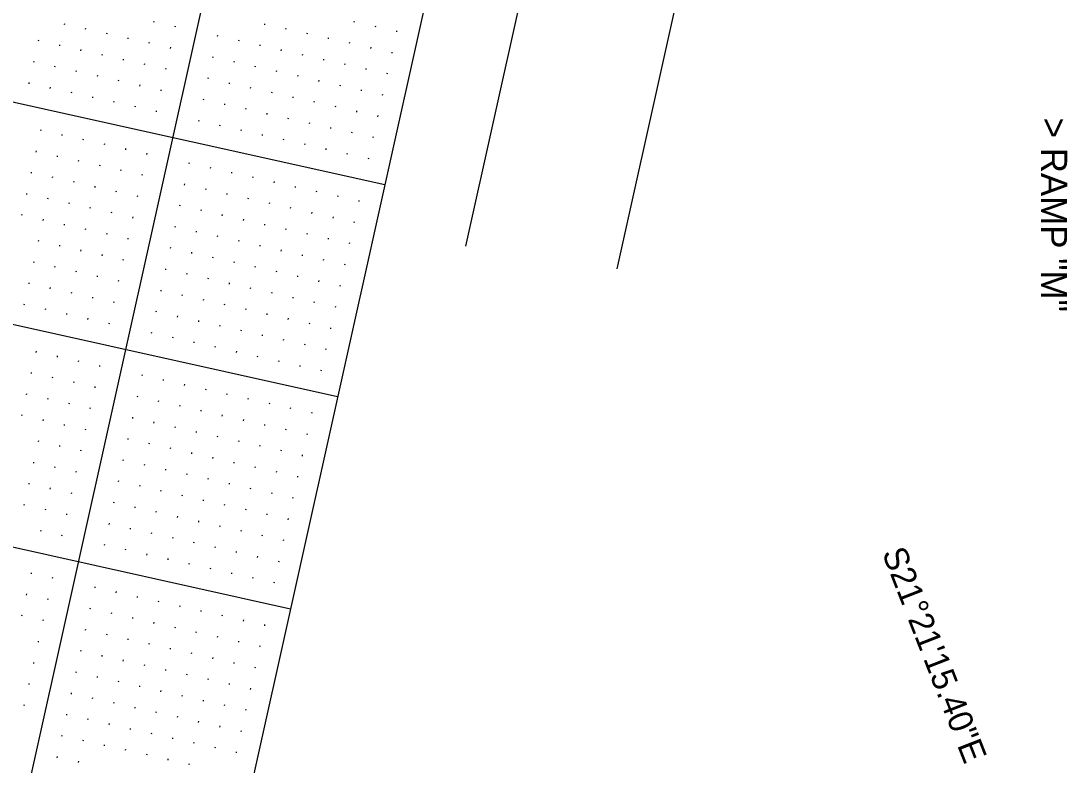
# Model space of a CAD drawing. Extents: x 2149268 to 2150830, y 142155 to 144285.
# Drawn here: x 2149963 to 2150201.6, y 143013.1 to 143184.5 of the extents above; entities that cross this region are included whole.
import ezdxf

# ---------------------------------------------------------------- set-up
doc = ezdxf.new("R2010")
doc.units = 0
for name, color, linetype in [('PR_Align_Ramp_M_Label', 7, 'Continuous'), ('PR_Align_Ramp_M_Leader', 7, 'Continuous'), ('SHT_Profile_Grid_Major', 7, 'Continuous'), ('SHT_Profile_Grid_Minor', 7, 'Continuous'), ('SHT_Sheet_Border', 7, 'Continuous')]:
    doc.layers.add(name, color=color, linetype=linetype)

msp = doc.modelspace()

# ---------------------------------------------------------------- linework, layer by layer
at = {"layer": 'PR_Align_Ramp_M_Leader'}
for points in [[(2150242.97, 143380.57), (2150121.59, 143385.32), (2150065.39, 143132.57)], [(2150212.94, 143229.67), (2150185.56, 143322.04), (2150145.43, 143330.97), (2150100.17, 143127.41)]]:
    msp.add_lwpolyline(points, dxfattribs=at)
at = {"layer": 'SHT_Profile_Grid_Major'}
for p, q in [((2150158.06, 143877.55), (2149816.2, 142340.1)), ((2149558.71, 143255.31), (2150046.79, 143146.78)), ((2149547.86, 143206.5), (2150035.94, 143097.97)), ((2149537.01, 143157.69), (2150025.09, 143049.16)), ((2149537.01, 143157.69), (2150025.09, 143049.16))]:
    msp.add_line(p, q, dxfattribs=at)
at = {"layer": 'SHT_Profile_Grid_Minor'}
for p, q in [((2149973.07, 143183.79), (2149973.01, 143183.54)), ((2149993.67, 143184.33), (2149993.62, 143184.08)), ((2149998.56, 143183.24), (2149998.5, 143183)), ((2150019.16, 143183.78), (2150019.11, 143183.54)), ((2150039.77, 143184.32), (2150039.72, 143184.08)), ((2150044.65, 143183.24), (2150044.6, 143182.99)), ((2149977.95, 143182.7), (2149977.89, 143182.46)), ((2149982.83, 143181.62), (2149982.77, 143181.37)), ((2149987.71, 143180.53), (2149987.65, 143180.29)), ((2150008.32, 143181.07), (2150008.26, 143180.83)), ((2150024.05, 143182.7), (2150023.99, 143182.45)), ((2150028.93, 143181.61), (2150028.87, 143181.37)), ((2150033.81, 143180.53), (2150033.75, 143180.28)), ((2150049.53, 143182.15), (2150049.48, 143181.91)), ((2149967.1, 143179.99), (2149967.05, 143179.75)), ((2149971.98, 143178.91), (2149971.93, 143178.66)), ((2149992.59, 143179.45), (2149992.54, 143179.2)), ((2149997.47, 143178.36), (2149997.42, 143178.12)), ((2150013.2, 143179.99), (2150013.14, 143179.74)), ((2150018.08, 143178.9), (2150018.02, 143178.66)), ((2150038.69, 143179.44), (2150038.63, 143179.2)), ((2150043.57, 143178.36), (2150043.51, 143178.11)), ((2149976.86, 143177.82), (2149976.81, 143177.58)), ((2149981.74, 143176.74), (2149981.69, 143176.49)), ((2150007.23, 143176.19), (2150007.18, 143175.95)), ((2150022.96, 143177.82), (2150022.91, 143177.57)), ((2150027.84, 143176.73), (2150027.79, 143176.49)), ((2150048.45, 143177.27), (2150048.39, 143177.03)), ((2149966.02, 143175.11), (2149965.96, 143174.87)), ((2149970.9, 143174.03), (2149970.84, 143173.78)), ((2149986.62, 143175.65), (2149986.57, 143175.41)), ((2149991.5, 143174.57), (2149991.45, 143174.32)), ((2149996.39, 143173.48), (2149996.33, 143173.24)), ((2150012.11, 143175.11), (2150012.06, 143174.86)), ((2150016.99, 143174.02), (2150016.94, 143173.78)), ((2150032.72, 143175.65), (2150032.67, 143175.4)), ((2150037.6, 143174.56), (2150037.55, 143174.32)), ((2150042.48, 143173.47), (2150042.43, 143173.23)), ((2149975.78, 143172.94), (2149975.72, 143172.7)), ((2149980.66, 143171.86), (2149980.6, 143171.61)), ((2150006.15, 143171.31), (2150006.09, 143171.07)), ((2150021.87, 143172.94), (2150021.82, 143172.69)), ((2150026.76, 143171.85), (2150026.7, 143171.61)), ((2150047.36, 143172.39), (2150047.31, 143172.15)), ((2149964.93, 143170.23), (2149964.88, 143169.99)), ((2149969.81, 143169.15), (2149969.76, 143168.9)), ((2149985.54, 143170.77), (2149985.48, 143170.53)), ((2149990.42, 143169.69), (2149990.36, 143169.44)), ((2149995.3, 143168.6), (2149995.25, 143168.36)), ((2150011.03, 143170.22), (2150010.97, 143169.98)), ((2150015.91, 143169.14), (2150015.85, 143168.9)), ((2150031.64, 143170.76), (2150031.58, 143170.52)), ((2150036.52, 143169.68), (2150036.46, 143169.44)), ((2150041.4, 143168.59), (2150041.34, 143168.35)), ((2149974.69, 143168.06), (2149974.64, 143167.82)), ((2149979.57, 143166.97), (2149979.52, 143166.73)), ((2150005.06, 143166.43), (2150005.01, 143166.19)), ((2150020.79, 143168.05), (2150020.73, 143167.81)), ((2150025.67, 143166.97), (2150025.62, 143166.72)), ((2150046.28, 143167.51), (2150046.22, 143167.26)), ((2149984.45, 143165.89), (2149984.4, 143165.65)), ((2149989.33, 143164.8), (2149989.28, 143164.56)), ((2150009.94, 143165.34), (2150009.89, 143165.1)), ((2150014.82, 143164.26), (2150014.77, 143164.01)), ((2150030.55, 143165.88), (2150030.5, 143165.64)), ((2150035.43, 143164.8), (2150035.38, 143164.55)), ((2149994.21, 143163.72), (2149994.16, 143163.48)), ((2150003.98, 143161.55), (2150003.92, 143161.3)), ((2150019.7, 143163.17), (2150019.65, 143162.93)), ((2150024.58, 143162.09), (2150024.53, 143161.84)), ((2150040.31, 143163.71), (2150040.26, 143163.47)), ((2150045.19, 143162.63), (2150045.14, 143162.38)), ((2149967.64, 143159.38), (2149967.59, 143159.14)), ((2150008.86, 143160.46), (2150008.8, 143160.22)), ((2150013.74, 143159.38), (2150013.68, 143159.13)), ((2150029.47, 143161), (2150029.41, 143160.76)), ((2150034.35, 143159.92), (2150034.29, 143159.67)), ((2149972.52, 143158.3), (2149972.47, 143158.05)), ((2149977.4, 143157.21), (2149977.35, 143156.97)), ((2150018.62, 143158.29), (2150018.56, 143158.05)), ((2150023.5, 143157.21), (2150023.45, 143156.96)), ((2150039.23, 143158.83), (2150039.17, 143158.59)), ((2150044.11, 143157.75), (2150044.05, 143157.5)), ((2149966.55, 143154.5), (2149966.5, 143154.26)), ((2149982.28, 143156.13), (2149982.23, 143155.88)), ((2149987.16, 143155.04), (2149987.11, 143154.8)), ((2150028.38, 143156.12), (2150028.33, 143155.88)), ((2150033.26, 143155.04), (2150033.21, 143154.79)), ((2149971.44, 143153.42), (2149971.38, 143153.17)), ((2149976.32, 143152.33), (2149976.26, 143152.09)), ((2149992.04, 143153.96), (2149991.99, 143153.71)), ((2150038.14, 143153.95), (2150038.09, 143153.71)), ((2150043.02, 143152.87), (2150042.97, 143152.62)), ((2149965.47, 143149.62), (2149965.42, 143149.38)), ((2149981.2, 143151.25), (2149981.14, 143151)), ((2149986.08, 143150.16), (2149986.02, 143149.92)), ((2150001.81, 143151.79), (2150001.75, 143151.54)), ((2150006.69, 143150.7), (2150006.63, 143150.46)), ((2150011.57, 143149.62), (2150011.51, 143149.37)), ((2149970.35, 143148.54), (2149970.3, 143148.29)), ((2149975.23, 143147.45), (2149975.18, 143147.21)), ((2149990.96, 143149.08), (2149990.9, 143148.83)), ((2150016.45, 143148.53), (2150016.39, 143148.29)), ((2150021.33, 143147.45), (2150021.27, 143147.2)), ((2149964.38, 143144.74), (2149964.33, 143144.5)), ((2149980.11, 143146.37), (2149980.06, 143146.12)), ((2149984.99, 143145.28), (2149984.94, 143145.04)), ((2150000.72, 143146.91), (2150000.67, 143146.66)), ((2150005.6, 143145.82), (2150005.55, 143145.58)), ((2150010.48, 143144.74), (2150010.43, 143144.49)), ((2150026.21, 143146.36), (2150026.16, 143146.12)), ((2150031.09, 143145.28), (2150031.04, 143145.03)), ((2149969.27, 143143.66), (2149969.21, 143143.41)), ((2149974.15, 143142.57), (2149974.09, 143142.33)), ((2149989.87, 143144.2), (2149989.82, 143143.95)), ((2150015.36, 143143.65), (2150015.31, 143143.41)), ((2150020.24, 143142.56), (2150020.19, 143142.32)), ((2150035.97, 143144.19), (2150035.92, 143143.95)), ((2150040.85, 143143.1), (2150040.8, 143142.86)), ((2149979.03, 143141.49), (2149978.97, 143141.24)), ((2149983.91, 143140.4), (2149983.85, 143140.16)), ((2149999.64, 143142.03), (2149999.58, 143141.78)), ((2150004.52, 143140.94), (2150004.46, 143140.7)), ((2150025.12, 143141.48), (2150025.07, 143141.24)), ((2150030.01, 143140.39), (2150029.95, 143140.15)), ((2149963.3, 143139.86), (2149963.24, 143139.62)), ((2149968.18, 143138.78), (2149968.13, 143138.53)), ((2149973.06, 143137.69), (2149973.01, 143137.45)), ((2149988.79, 143139.32), (2149988.73, 143139.07)), ((2150009.4, 143139.85), (2150009.34, 143139.61)), ((2150014.28, 143138.77), (2150014.22, 143138.53)), ((2150019.16, 143137.68), (2150019.1, 143137.44)), ((2150034.89, 143139.31), (2150034.83, 143139.07)), ((2150039.77, 143138.22), (2150039.71, 143137.98)), ((2149977.94, 143136.6), (2149977.89, 143136.36)), ((2149982.82, 143135.52), (2149982.77, 143135.28)), ((2149998.55, 143137.14), (2149998.5, 143136.9)), ((2150003.43, 143136.06), (2150003.38, 143135.82)), ((2150024.04, 143136.6), (2150023.98, 143136.35)), ((2150028.92, 143135.51), (2150028.87, 143135.27)), ((2149967.09, 143133.89), (2149967.04, 143133.65)), ((2149971.98, 143132.81), (2149971.92, 143132.57)), ((2149987.7, 143134.43), (2149987.65, 143134.19)), ((2150008.31, 143134.97), (2150008.26, 143134.73)), ((2150013.19, 143133.89), (2150013.14, 143133.64)), ((2150018.07, 143132.8), (2150018.02, 143132.56)), ((2150033.8, 143134.43), (2150033.75, 143134.18)), ((2150038.68, 143133.34), (2150038.63, 143133.1)), ((2149976.86, 143131.72), (2149976.8, 143131.48)), ((2149981.74, 143130.64), (2149981.68, 143130.39)), ((2149997.46, 143132.26), (2149997.41, 143132.02)), ((2150002.35, 143131.18), (2150002.29, 143130.93)), ((2150022.95, 143131.72), (2150022.9, 143131.47)), ((2150027.83, 143130.63), (2150027.78, 143130.39)), ((2149966.01, 143129.01), (2149965.96, 143128.77)), ((2149986.62, 143129.55), (2149986.56, 143129.31)), ((2150007.23, 143130.09), (2150007.17, 143129.85)), ((2150012.11, 143129.01), (2150012.05, 143128.76)), ((2150032.72, 143129.55), (2150032.66, 143129.3)), ((2150037.6, 143128.46), (2150037.54, 143128.22)), ((2149970.89, 143127.93), (2149970.84, 143127.68)), ((2149975.77, 143126.84), (2149975.72, 143126.6)), ((2149980.65, 143125.76), (2149980.6, 143125.51)), ((2149996.38, 143127.38), (2149996.33, 143127.14)), ((2150001.26, 143126.3), (2150001.21, 143126.05)), ((2150016.99, 143127.92), (2150016.93, 143127.68)), ((2150021.87, 143126.84), (2150021.81, 143126.59)), ((2150026.75, 143125.75), (2150026.7, 143125.51)), ((2149964.92, 143124.13), (2149964.87, 143123.89)), ((2149985.53, 143124.67), (2149985.48, 143124.43)), ((2150006.14, 143125.21), (2150006.09, 143124.97)), ((2150011.02, 143124.13), (2150010.97, 143123.88)), ((2150031.63, 143124.67), (2150031.58, 143124.42)), ((2150036.51, 143123.58), (2150036.46, 143123.34)), ((2149969.8, 143123.05), (2149969.75, 143122.8)), ((2149974.69, 143121.96), (2149974.63, 143121.72)), ((2149979.57, 143120.88), (2149979.51, 143120.63)), ((2149995.29, 143122.5), (2149995.24, 143122.26)), ((2150000.17, 143121.42), (2150000.12, 143121.17)), ((2150015.9, 143123.04), (2150015.85, 143122.8)), ((2150020.78, 143121.96), (2150020.73, 143121.71)), ((2149963.84, 143119.25), (2149963.78, 143119.01)), ((2149984.45, 143119.79), (2149984.39, 143119.55)), ((2150005.06, 143120.33), (2150005, 143120.09)), ((2150009.94, 143119.25), (2150009.88, 143119)), ((2150025.66, 143120.87), (2150025.61, 143120.63)), ((2150030.54, 143119.79), (2150030.49, 143119.54)), ((2150035.43, 143118.7), (2150035.37, 143118.46)), ((2149968.72, 143118.17), (2149968.67, 143117.92)), ((2149973.6, 143117.08), (2149973.55, 143116.84)), ((2149994.21, 143117.62), (2149994.15, 143117.38)), ((2149999.09, 143116.54), (2149999.04, 143116.29)), ((2150014.82, 143118.16), (2150014.76, 143117.92)), ((2150019.7, 143117.08), (2150019.64, 143116.83)), ((2149978.48, 143116), (2149978.43, 143115.75)), ((2149983.36, 143114.91), (2149983.31, 143114.67)), ((2150003.97, 143115.45), (2150003.92, 143115.21)), ((2150008.85, 143114.37), (2150008.8, 143114.12)), ((2150024.58, 143115.99), (2150024.52, 143115.75)), ((2150029.46, 143114.91), (2150029.41, 143114.66)), ((2150034.34, 143113.82), (2150034.29, 143113.58)), ((2149993.12, 143112.74), (2149993.07, 143112.5)), ((2149998, 143111.66), (2149997.95, 143111.41)), ((2150013.73, 143113.28), (2150013.68, 143113.04)), ((2150018.61, 143112.2), (2150018.56, 143111.95)), ((2150002.89, 143110.57), (2150002.83, 143110.33)), ((2150007.77, 143109.48), (2150007.71, 143109.24)), ((2150023.49, 143111.11), (2150023.44, 143110.87)), ((2150028.37, 143110.02), (2150028.32, 143109.78)), ((2149966.55, 143108.41), (2149966.49, 143108.16)), ((2149971.43, 143107.32), (2149971.38, 143107.08)), ((2150012.65, 143108.4), (2150012.59, 143108.16)), ((2150017.53, 143107.31), (2150017.47, 143107.07)), ((2150033.26, 143108.94), (2150033.2, 143108.7)), ((2149976.31, 143106.23), (2149976.26, 143105.99)), ((2149981.19, 143105.15), (2149981.14, 143104.91)), ((2150022.41, 143106.23), (2150022.35, 143105.98)), ((2150027.29, 143105.14), (2150027.23, 143104.9)), ((2149965.46, 143103.52), (2149965.41, 143103.28)), ((2149970.34, 143102.44), (2149970.29, 143102.2)), ((2149990.95, 143102.98), (2149990.9, 143102.73)), ((2149995.83, 143101.89), (2149995.78, 143101.65)), ((2150032.17, 143104.06), (2150032.12, 143103.81)), ((2149975.23, 143101.35), (2149975.17, 143101.11)), ((2149980.11, 143100.27), (2149980.05, 143100.02)), ((2150000.71, 143100.81), (2150000.66, 143100.56)), ((2150005.6, 143099.72), (2150005.54, 143099.48)), ((2149964.38, 143098.64), (2149964.32, 143098.4)), ((2149969.26, 143097.56), (2149969.2, 143097.31)), ((2149989.87, 143098.1), (2149989.81, 143097.85)), ((2150010.48, 143098.64), (2150010.42, 143098.39)), ((2150015.36, 143097.55), (2150015.3, 143097.31)), ((2149974.14, 143096.47), (2149974.09, 143096.23)), ((2149979.02, 143095.39), (2149978.97, 143095.14)), ((2149994.75, 143097.01), (2149994.69, 143096.77)), ((2149999.63, 143095.93), (2149999.57, 143095.68)), ((2150004.51, 143094.84), (2150004.46, 143094.6)), ((2150020.24, 143096.47), (2150020.18, 143096.22)), ((2150025.12, 143095.38), (2150025.06, 143095.14)), ((2149963.29, 143093.76), (2149963.24, 143093.52)), ((2149968.17, 143092.68), (2149968.12, 143092.43)), ((2149988.78, 143093.22), (2149988.73, 143092.97)), ((2150009.39, 143093.76), (2150009.34, 143093.51)), ((2150014.27, 143092.67), (2150014.22, 143092.43)), ((2150030, 143094.3), (2150029.94, 143094.05)), ((2149973.05, 143091.59), (2149973, 143091.35)), ((2149977.94, 143090.51), (2149977.88, 143090.26)), ((2149993.66, 143092.13), (2149993.61, 143091.89)), ((2149998.54, 143091.05), (2149998.49, 143090.8)), ((2150003.42, 143089.96), (2150003.37, 143089.72)), ((2150019.15, 143091.59), (2150019.1, 143091.34)), ((2150024.03, 143090.5), (2150023.98, 143090.26)), ((2149967.09, 143087.8), (2149967.03, 143087.55)), ((2149987.7, 143088.34), (2149987.64, 143088.09)), ((2150008.31, 143088.88), (2150008.25, 143088.63)), ((2150013.19, 143087.79), (2150013.13, 143087.55)), ((2150028.91, 143089.42), (2150028.86, 143089.17)), ((2149971.97, 143086.71), (2149971.92, 143086.47)), ((2149976.85, 143085.63), (2149976.8, 143085.38)), ((2149992.58, 143087.25), (2149992.52, 143087.01)), ((2149997.46, 143086.17), (2149997.4, 143085.92)), ((2150018.07, 143086.71), (2150018.01, 143086.46)), ((2150022.95, 143085.62), (2150022.89, 143085.38)), ((2149966, 143082.92), (2149965.95, 143082.67)), ((2149986.61, 143083.46), (2149986.56, 143083.21)), ((2150002.34, 143085.08), (2150002.29, 143084.84)), ((2150007.22, 143084), (2150007.17, 143083.75)), ((2150012.1, 143082.91), (2150012.05, 143082.67)), ((2150027.83, 143084.54), (2150027.77, 143084.29)), ((2149970.88, 143081.83), (2149970.83, 143081.59)), ((2149975.76, 143080.75), (2149975.71, 143080.5)), ((2149991.49, 143082.37), (2149991.44, 143082.13)), ((2149996.37, 143081.29), (2149996.32, 143081.04)), ((2150016.98, 143081.82), (2150016.93, 143081.58)), ((2150021.86, 143080.74), (2150021.81, 143080.5)), ((2149964.92, 143078.04), (2149964.86, 143077.79)), ((2149985.53, 143078.58), (2149985.47, 143078.33)), ((2150001.25, 143080.2), (2150001.2, 143079.96)), ((2150006.13, 143079.11), (2150006.08, 143078.87)), ((2150011.02, 143078.03), (2150010.96, 143077.79)), ((2150026.74, 143079.65), (2150026.69, 143079.41)), ((2149969.8, 143076.95), (2149969.74, 143076.71)), ((2149974.68, 143075.86), (2149974.63, 143075.62)), ((2149990.41, 143077.49), (2149990.35, 143077.25)), ((2149995.29, 143076.4), (2149995.23, 143076.16)), ((2150015.9, 143076.94), (2150015.84, 143076.7)), ((2150020.78, 143075.86), (2150020.72, 143075.61)), ((2149984.44, 143073.69), (2149984.39, 143073.45)), ((2150000.17, 143075.32), (2150000.11, 143075.08)), ((2150005.05, 143074.23), (2150005, 143073.99)), ((2150025.66, 143074.77), (2150025.6, 143074.53)), ((2149963.83, 143073.15), (2149963.78, 143072.91)), ((2149968.71, 143072.07), (2149968.66, 143071.83)), ((2149973.59, 143070.98), (2149973.54, 143070.74)), ((2149989.32, 143072.61), (2149989.27, 143072.36)), ((2149994.2, 143071.52), (2149994.15, 143071.28)), ((2150009.93, 143073.15), (2150009.88, 143072.9)), ((2150014.81, 143072.06), (2150014.76, 143071.82)), ((2150019.69, 143070.98), (2150019.64, 143070.73)), ((2149983.36, 143068.81), (2149983.3, 143068.57)), ((2149999.08, 143070.44), (2149999.03, 143070.19)), ((2150003.96, 143069.35), (2150003.91, 143069.11)), ((2150024.57, 143069.89), (2150024.52, 143069.65)), ((2149967.63, 143067.19), (2149967.57, 143066.94)), ((2149972.51, 143066.1), (2149972.45, 143065.86)), ((2149988.24, 143067.73), (2149988.18, 143067.48)), ((2149993.12, 143066.64), (2149993.06, 143066.4)), ((2150008.85, 143068.27), (2150008.79, 143068.02)), ((2150013.73, 143067.18), (2150013.67, 143066.94)), ((2150018.61, 143066.1), (2150018.55, 143065.85)), ((2149982.27, 143063.93), (2149982.22, 143063.69)), ((2149998, 143065.56), (2149997.94, 143065.31)), ((2150002.88, 143064.47), (2150002.82, 143064.23)), ((2150023.49, 143065.01), (2150023.43, 143064.77)), ((2149987.15, 143062.85), (2149987.1, 143062.6)), ((2149992.03, 143061.76), (2149991.98, 143061.52)), ((2150007.76, 143063.39), (2150007.71, 143063.14)), ((2150012.64, 143062.3), (2150012.59, 143062.06)), ((2149996.91, 143060.68), (2149996.86, 143060.43)), ((2150001.79, 143059.59), (2150001.74, 143059.35)), ((2150017.52, 143061.22), (2150017.47, 143060.97)), ((2150022.4, 143060.13), (2150022.35, 143059.89)), ((2149965.46, 143057.43), (2149965.4, 143057.18)), ((2150006.67, 143058.51), (2150006.62, 143058.26)), ((2150011.56, 143057.42), (2150011.5, 143057.18)), ((2149970.34, 143056.34), (2149970.28, 143056.1)), ((2149980.1, 143054.17), (2149980.05, 143053.93)), ((2150016.44, 143056.34), (2150016.38, 143056.09)), ((2150021.32, 143055.25), (2150021.26, 143055.01)), ((2149964.37, 143052.55), (2149964.32, 143052.3)), ((2149984.98, 143053.09), (2149984.93, 143052.84)), ((2149989.86, 143052), (2149989.81, 143051.76)), ((2149969.25, 143051.46), (2149969.2, 143051.22)), ((2149994.74, 143050.92), (2149994.69, 143050.67)), ((2149999.62, 143049.83), (2149999.57, 143049.59)), ((2149963.29, 143047.67), (2149963.23, 143047.42)), ((2149979.01, 143049.29), (2149978.96, 143049.05)), ((2149983.9, 143048.2), (2149983.84, 143047.96)), ((2149988.78, 143047.12), (2149988.72, 143046.88)), ((2150004.5, 143048.74), (2150004.45, 143048.5)), ((2150009.38, 143047.66), (2150009.33, 143047.42)), ((2149968.17, 143046.58), (2149968.11, 143046.34)), ((2149993.66, 143046.03), (2149993.6, 143045.79)), ((2149998.54, 143044.95), (2149998.48, 143044.71)), ((2150014.27, 143046.57), (2150014.21, 143046.33)), ((2150019.15, 143045.49), (2150019.09, 143045.24)), ((2149977.93, 143044.41), (2149977.88, 143044.17)), ((2149982.81, 143043.32), (2149982.76, 143043.08)), ((2149987.69, 143042.24), (2149987.64, 143041.99)), ((2150003.42, 143043.86), (2150003.36, 143043.62)), ((2150008.3, 143042.78), (2150008.25, 143042.53)), ((2149967.08, 143041.7), (2149967.03, 143041.46)), ((2149992.57, 143041.15), (2149992.52, 143040.91)), ((2149997.45, 143040.07), (2149997.4, 143039.82)), ((2150013.18, 143041.69), (2150013.13, 143041.45)), ((2150018.06, 143040.61), (2150018.01, 143040.36)), ((2149976.84, 143039.53), (2149976.79, 143039.28)), ((2149981.73, 143038.44), (2149981.67, 143038.2)), ((2150002.33, 143038.98), (2150002.28, 143038.74)), ((2150007.21, 143037.9), (2150007.16, 143037.65)), ((2149966, 143036.82), (2149965.94, 143036.57)), ((2149986.61, 143037.36), (2149986.55, 143037.11)), ((2149991.49, 143036.27), (2149991.43, 143036.03)), ((2149996.37, 143035.19), (2149996.31, 143034.94)), ((2150012.1, 143036.81), (2150012.04, 143036.57)), ((2150016.98, 143035.73), (2150016.92, 143035.48)), ((2149975.76, 143034.65), (2149975.7, 143034.4)), ((2149980.64, 143033.56), (2149980.59, 143033.32)), ((2150001.25, 143034.1), (2150001.19, 143033.86)), ((2150006.13, 143033.02), (2150006.07, 143032.77)), ((2149964.91, 143031.94), (2149964.86, 143031.69)), ((2149985.52, 143032.48), (2149985.47, 143032.23)), ((2149990.4, 143031.39), (2149990.35, 143031.15)), ((2149995.28, 143030.31), (2149995.23, 143030.06)), ((2150011.01, 143031.93), (2150010.96, 143031.69)), ((2150015.89, 143030.85), (2150015.84, 143030.6)), ((2149974.67, 143029.77), (2149974.62, 143029.52)), ((2149979.55, 143028.68), (2149979.5, 143028.44)), ((2150000.16, 143029.22), (2150000.11, 143028.98)), ((2150005.04, 143028.14), (2150004.99, 143027.89)), ((2149963.83, 143027.06), (2149963.77, 143026.81)), ((2149984.44, 143027.6), (2149984.38, 143027.35)), ((2149989.32, 143026.51), (2149989.26, 143026.27)), ((2150009.92, 143027.05), (2150009.87, 143026.81)), ((2150014.81, 143025.97), (2150014.75, 143025.72)), ((2149973.59, 143024.89), (2149973.53, 143024.64)), ((2149978.47, 143023.8), (2149978.42, 143023.56)), ((2149994.2, 143025.43), (2149994.14, 143025.18)), ((2149999.08, 143024.34), (2149999.02, 143024.1)), ((2150003.96, 143023.26), (2150003.9, 143023.01)), ((2149983.35, 143022.72), (2149983.3, 143022.47)), ((2149988.23, 143021.63), (2149988.18, 143021.39)), ((2150008.84, 143022.17), (2150008.79, 143021.93)), ((2150013.72, 143021.08), (2150013.67, 143020.84)), ((2149972.5, 143020.01), (2149972.45, 143019.76)), ((2149977.38, 143018.92), (2149977.33, 143018.68)), ((2149993.11, 143020.55), (2149993.06, 143020.3)), ((2149997.99, 143019.46), (2149997.94, 143019.22)), ((2150002.87, 143018.37), (2150002.82, 143018.13)), ((2149982.26, 143017.83), (2149982.21, 143017.59)), ((2149987.15, 143016.75), (2149987.09, 143016.51)), ((2150007.75, 143017.29), (2150007.7, 143017.05)), ((2150012.63, 143016.2), (2150012.58, 143015.96)), ((2149971.42, 143015.12), (2149971.36, 143014.88)), ((2149976.3, 143014.04), (2149976.24, 143013.8)), ((2149992.03, 143015.66), (2149991.97, 143015.42)), ((2149996.91, 143014.58), (2149996.85, 143014.34)), ((2150001.79, 143013.49), (2150001.73, 143013.25))]:
    msp.add_line(p, q, dxfattribs=at)
at = {"layer": 'SHT_Sheet_Border'}
msp.add_line((2150206.87, 143866.7), (2149865.01, 142329.24), dxfattribs=at)

# ---------------------------------------------------------------- texts
at = {"layer": 'PR_Align_Ramp_M_Label'}
for s, height, rotation, p in [('> RAMP "M"', 6, 269.9405, (2150197.85, 143162.16)), ('S21%%d21\'15.40"E', 5.6, 291.3543, (2150161.16, 143062.01))]:
    msp.add_text(s, height=height, rotation=rotation, dxfattribs=at).set_placement(p)

doc.saveas('drawing.dxf')
